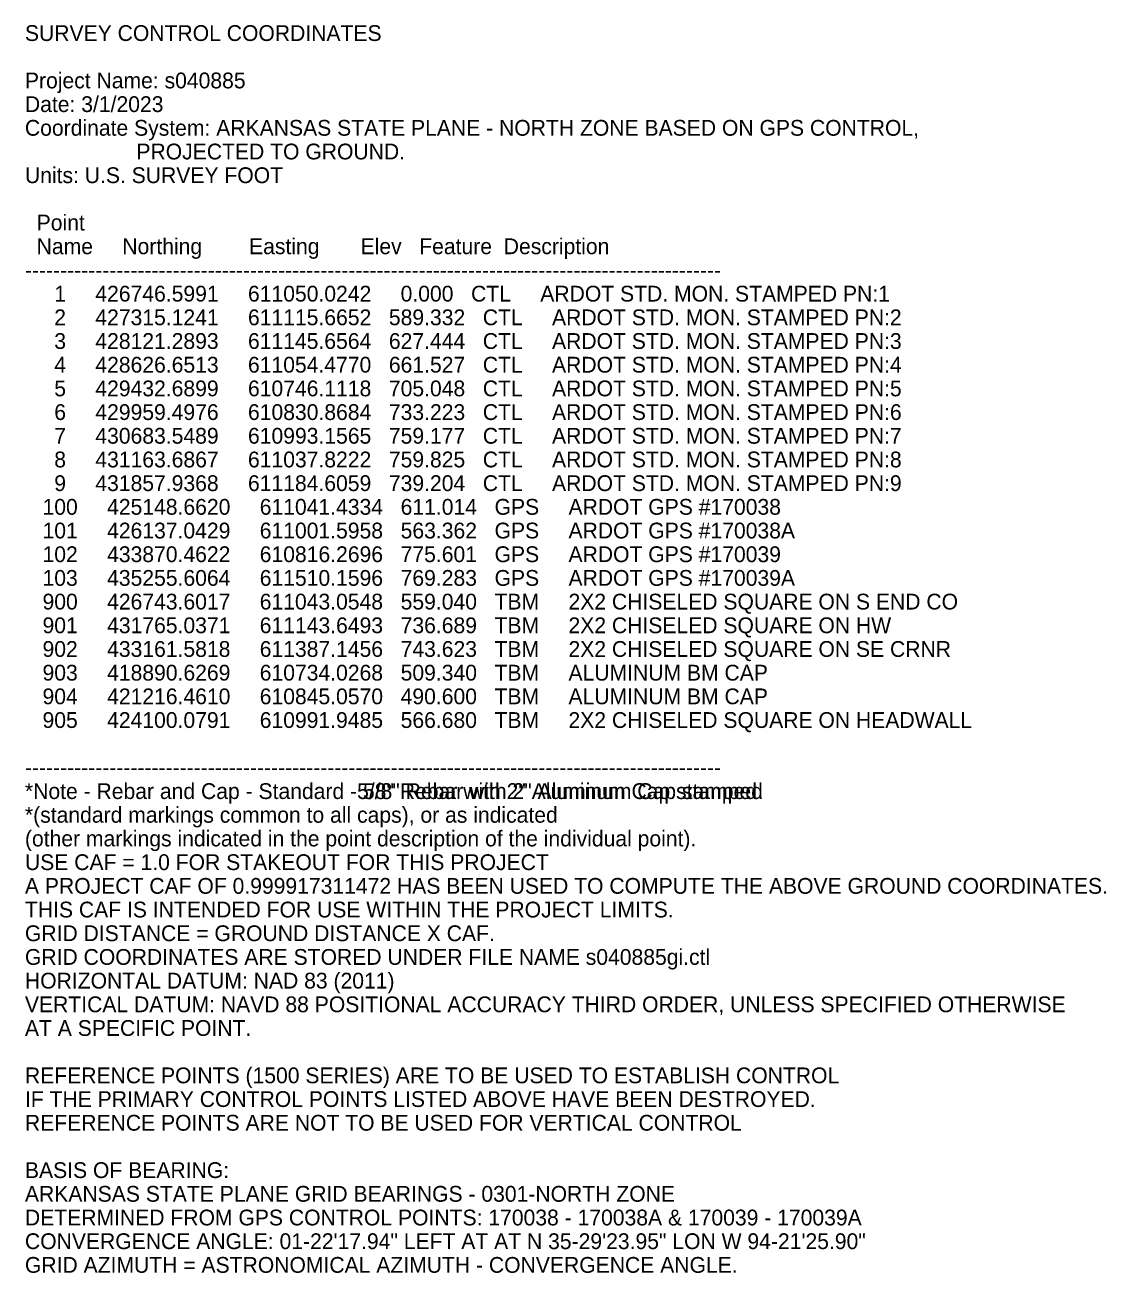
# Model space of a CAD drawing. Extents: x 608192 to 612822, y 418871 to 435264.
# Drawn here: x 608663.7 to 609006, y 430271 to 430666.2 of the extents above; entities that cross this region are included whole.
import ezdxf

# ---------------------------------------------------------------- set-up
doc = ezdxf.new("R2010")
doc.units = 0
doc.layers.add('Default', color=7, linetype='Continuous')

msp = doc.modelspace()

# ---------------------------------------------------------------- texts
at = {"layer": 'Default'}
for s, p in [('SURVEY CONTROL COORDINATES ', (608663.7, 430661.12)), ('SURVEY CONTROL COORDINATES ', (608663.7, 430661.12)), ('Project Name: s040885 ', (608663.7, 430646.12)), ('Project Name: s040885 ', (608663.7, 430646.12)), ('Date: 3/1/2023 ', (608663.7, 430638.62)), ('Date: 3/1/2023 ', (608663.7, 430638.62)), ('Coordinate System: ARKANSAS STATE PLANE - NORTH ZONE BASED ON GPS CONTROL, ', (608663.7, 430631.12)), ('Coordinate System: ARKANSAS STATE PLANE - NORTH ZONE BASED ON GPS CONTROL, ', (608663.7, 430631.12)), ('                   PROJECTED TO GROUND. ', (608663.7, 430623.62)), ('                   PROJECTED TO GROUND. ', (608663.7, 430623.62)), ('Units: U.S. SURVEY FOOT ', (608663.7, 430616.12)), ('Units: U.S. SURVEY FOOT ', (608663.7, 430616.12)), ('  Point ', (608663.7, 430601.12)), ('  Point ', (608663.7, 430601.12)), ('  Name     Northing        Easting       Elev   Feature  Description ', (608663.7, 430593.62)), ('  Name     Northing        Easting       Elev   Feature  Description ', (608663.7, 430593.62)), ('--------------------------------------------------------------------------------------------------- ', (608663.7, 430586.12)), ('--------------------------------------------------------------------------------------------------- ', (608663.7, 430586.12)), ('     1     426746.5991     611050.0242     0.000   CTL    \xa0ARDOT STD. MON. STAMPED PN:1 ', (608663.7, 430578.62)), ('     1     426746.5991     611050.0242     0.000   CTL    \xa0ARDOT STD. MON. STAMPED PN:1 ', (608663.7, 430578.62)), ('     2     427315.1241     611115.6652   589.332   CTL    \xa0ARDOT STD. MON. STAMPED PN:2 ', (608663.7, 430571.12)), ('     2     427315.1241     611115.6652   589.332   CTL    \xa0ARDOT STD. MON. STAMPED PN:2 ', (608663.7, 430571.12)), ('     3     428121.2893     611145.6564   627.444   CTL    \xa0ARDOT STD. MON. STAMPED PN:3 ', (608663.7, 430563.62)), ('     3     428121.2893     611145.6564   627.444   CTL    \xa0ARDOT STD. MON. STAMPED PN:3 ', (608663.7, 430563.62)), ('     4     428626.6513     611054.4770   661.527   CTL    \xa0ARDOT STD. MON. STAMPED PN:4 ', (608663.7, 430556.12)), ('     4     428626.6513     611054.4770   661.527   CTL    \xa0ARDOT STD. MON. STAMPED PN:4 ', (608663.7, 430556.12)), ('     5     429432.6899     610746.1118   705.048   CTL    \xa0ARDOT STD. MON. STAMPED PN:5 ', (608663.7, 430548.62)), ('     5     429432.6899     610746.1118   705.048   CTL    \xa0ARDOT STD. MON. STAMPED PN:5 ', (608663.7, 430548.62)), ('     6     429959.4976     610830.8684   733.223   CTL    \xa0ARDOT STD. MON. STAMPED PN:6 ', (608663.7, 430541.12)), ('     6     429959.4976     610830.8684   733.223   CTL    \xa0ARDOT STD. MON. STAMPED PN:6 ', (608663.7, 430541.12)), ('     7     430683.5489     610993.1565   759.177   CTL    \xa0ARDOT STD. MON. STAMPED PN:7 ', (608663.7, 430533.62)), ('     7     430683.5489     610993.1565   759.177   CTL    \xa0ARDOT STD. MON. STAMPED PN:7 ', (608663.7, 430533.62)), ('     8     431163.6867     611037.8222   759.825   CTL    \xa0ARDOT STD. MON. STAMPED PN:8 ', (608663.7, 430526.12)), ('     8     431163.6867     611037.8222   759.825   CTL    \xa0ARDOT STD. MON. STAMPED PN:8 ', (608663.7, 430526.12)), ('     9     431857.9368     611184.6059   739.204   CTL    \xa0ARDOT STD. MON. STAMPED PN:9 ', (608663.7, 430518.62)), ('     9     431857.9368     611184.6059   739.204   CTL    \xa0ARDOT STD. MON. STAMPED PN:9 ', (608663.7, 430518.62)), ('   100     425148.6620     611041.4334   611.014   GPS    \xa0ARDOT GPS #170038 ', (608663.7, 430511.12)), ('   100     425148.6620     611041.4334   611.014   GPS    \xa0ARDOT GPS #170038 ', (608663.7, 430511.12)), ('   101     426137.0429     611001.5958   563.362   GPS    \xa0ARDOT GPS #170038A ', (608663.7, 430503.62)), ('   101     426137.0429     611001.5958   563.362   GPS    \xa0ARDOT GPS #170038A ', (608663.7, 430503.62)), ('   102     433870.4622     610816.2696   775.601   GPS    \xa0ARDOT GPS #170039 ', (608663.7, 430496.12)), ('   102     433870.4622     610816.2696   775.601   GPS    \xa0ARDOT GPS #170039 ', (608663.7, 430496.12)), ('   103     435255.6064     611510.1596   769.283   GPS    \xa0ARDOT GPS #170039A ', (608663.7, 430488.62)), ('   103     435255.6064     611510.1596   769.283   GPS    \xa0ARDOT GPS #170039A ', (608663.7, 430488.62)), ('   900     426743.6017     611043.0548   559.040   TBM    \xa02X2 CHISELED SQUARE ON S END CO ', (608663.7, 430481.12)), ('   900     426743.6017     611043.0548   559.040   TBM    \xa02X2 CHISELED SQUARE ON S END CO ', (608663.7, 430481.12)), ('   901     431765.0371     611143.6493   736.689   TBM    \xa02X2 CHISELED SQUARE ON HW ', (608663.7, 430473.62)), ('   901     431765.0371     611143.6493   736.689   TBM    \xa02X2 CHISELED SQUARE ON HW ', (608663.7, 430473.62)), ('   902     433161.5818     611387.1456   743.623   TBM    \xa02X2 CHISELED SQUARE ON SE CRNR  ', (608663.7, 430466.12)), ('   902     433161.5818     611387.1456   743.623   TBM    \xa02X2 CHISELED SQUARE ON SE CRNR  ', (608663.7, 430466.12)), ('   903     418890.6269     610734.0268   509.340   TBM    \xa0ALUMINUM BM CAP ', (608663.7, 430458.62)), ('   903     418890.6269     610734.0268   509.340   TBM    \xa0ALUMINUM BM CAP ', (608663.7, 430458.62)), ('   904     421216.4610     610845.0570   490.600   TBM    \xa0ALUMINUM BM CAP ', (608663.7, 430451.12)), ('   904     421216.4610     610845.0570   490.600   TBM    \xa0ALUMINUM BM CAP ', (608663.7, 430451.12)), ('   905     424100.0791     610991.9485   566.680   TBM    \xa02X2 CHISELED SQUARE ON HEADWALL ', (608663.7, 430443.62)), ('   905     424100.0791     610991.9485   566.680   TBM    \xa02X2 CHISELED SQUARE ON HEADWALL ', (608663.7, 430443.62)), ('--------------------------------------------------------------------------------------------------- ', (608663.7, 430428.62)), ('--------------------------------------------------------------------------------------------------- ', (608663.7, 430428.62)), ('*Note - Rebar and Cap - Standard -5/8" Rebar with 2" Aluminum Cap stamped ', (608663.7, 430421.12)), ('*Note - Rebar and Cap - Standard - 5/8" Rebar with 2" Aluminum Cap stamped ', (608663.7, 430421.12)), ('*(standard markings common to all caps), or as indicated ', (608663.7, 430413.62)), ('*(standard markings common to all caps), or as indicated ', (608663.7, 430413.62)), ('(other markings indicated in the point description of the individual point).  ', (608663.7, 430406.12)), ('(other markings indicated in the point description of the individual point).  ', (608663.7, 430406.12)), ('USE CAF = 1.0 FOR STAKEOUT FOR THIS PROJECT ', (608663.7, 430398.62)), ('USE CAF = 1.0 FOR STAKEOUT FOR THIS PROJECT ', (608663.7, 430398.62)), ('A PROJECT CAF OF 0.999917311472 HAS BEEN USED TO COMPUTE THE ABOVE GROUND COORDINATES. ', (608663.7, 430391.12)), ('A PROJECT CAF OF 0.999917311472 HAS BEEN USED TO COMPUTE THE ABOVE GROUND COORDINATES. ', (608663.7, 430391.12)), ('THIS CAF IS INTENDED FOR USE WITHIN THE PROJECT LIMITS. ', (608663.7, 430383.62)), ('THIS CAF IS INTENDED FOR USE WITHIN THE PROJECT LIMITS. ', (608663.7, 430383.62)), ('GRID DISTANCE = GROUND DISTANCE X CAF. ', (608663.7, 430376.12)), ('GRID DISTANCE = GROUND DISTANCE X CAF. ', (608663.7, 430376.12)), ('GRID COORDINATES ARE STORED UNDER FILE NAME s040885gi.ctl', (608663.7, 430368.62)), ('GRID COORDINATES ARE STORED UNDER FILE NAME s040885gi.ctl', (608663.7, 430368.62)), ('HORIZONTAL DATUM: NAD 83 (2011) ', (608663.7, 430361.12)), ('HORIZONTAL DATUM: NAD 83 (2011) ', (608663.7, 430361.12)), ('VERTICAL DATUM: NAVD 88 POSITIONAL ACCURACY THIRD ORDER, UNLESS SPECIFIED OTHERWISE  ', (608663.7, 430353.62)), ('VERTICAL DATUM: NAVD 88 POSITIONAL ACCURACY THIRD ORDER, UNLESS SPECIFIED OTHERWISE  ', (608663.7, 430353.62)), ('AT A SPECIFIC POINT. ', (608663.7, 430346.12)), ('AT A SPECIFIC POINT. ', (608663.7, 430346.12)), ('REFERENCE POINTS (1500 SERIES) ARE TO BE USED TO ESTABLISH CONTROL ', (608663.7, 430331.12)), ('REFERENCE POINTS (1500 SERIES) ARE TO BE USED TO ESTABLISH CONTROL ', (608663.7, 430331.12)), ('IF THE PRIMARY CONTROL POINTS LISTED ABOVE HAVE BEEN DESTROYED. ', (608663.7, 430323.62)), ('IF THE PRIMARY CONTROL POINTS LISTED ABOVE HAVE BEEN DESTROYED. ', (608663.7, 430323.62)), ('REFERENCE POINTS ARE NOT TO BE USED FOR VERTICAL CONTROL ', (608663.7, 430316.12)), ('REFERENCE POINTS ARE NOT TO BE USED FOR VERTICAL CONTROL ', (608663.7, 430316.12)), ('BASIS OF BEARING: ', (608663.7, 430301.12)), ('BASIS OF BEARING: ', (608663.7, 430301.12)), ('ARKANSAS STATE PLANE GRID BEARINGS - 0301-NORTH ZONE', (608663.7, 430293.62)), ('ARKANSAS STATE PLANE GRID BEARINGS - 0301-NORTH ZONE', (608663.7, 430293.62)), ('DETERMINED FROM GPS CONTROL POINTS: 170038 - 170038A & 170039 - 170039A ', (608663.7, 430286.12)), ('DETERMINED FROM GPS CONTROL POINTS: 170038 - 170038A & 170039 - 170039A ', (608663.7, 430286.12)), ('CONVERGENCE ANGLE: 01-22\'17.94" LEFT AT AT N 35-29\'23.95" LON W 94-21\'25.90" ', (608663.7, 430278.62)), ('CONVERGENCE ANGLE: 01-22\'17.94" LEFT AT AT N 35-29\'23.95" LON W 94-21\'25.90" ', (608663.7, 430278.62)), ('GRID AZIMUTH = ASTRONOMICAL AZIMUTH - CONVERGENCE ANGLE. ', (608663.7, 430271.12)), ('GRID AZIMUTH = ASTRONOMICAL AZIMUTH - CONVERGENCE ANGLE. ', (608663.7, 430271.12))]:
    msp.add_text(s, height=5, dxfattribs=at).set_placement(p)

doc.saveas('drawing.dxf')
